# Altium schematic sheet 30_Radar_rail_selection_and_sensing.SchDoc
size 289 x 396 mm
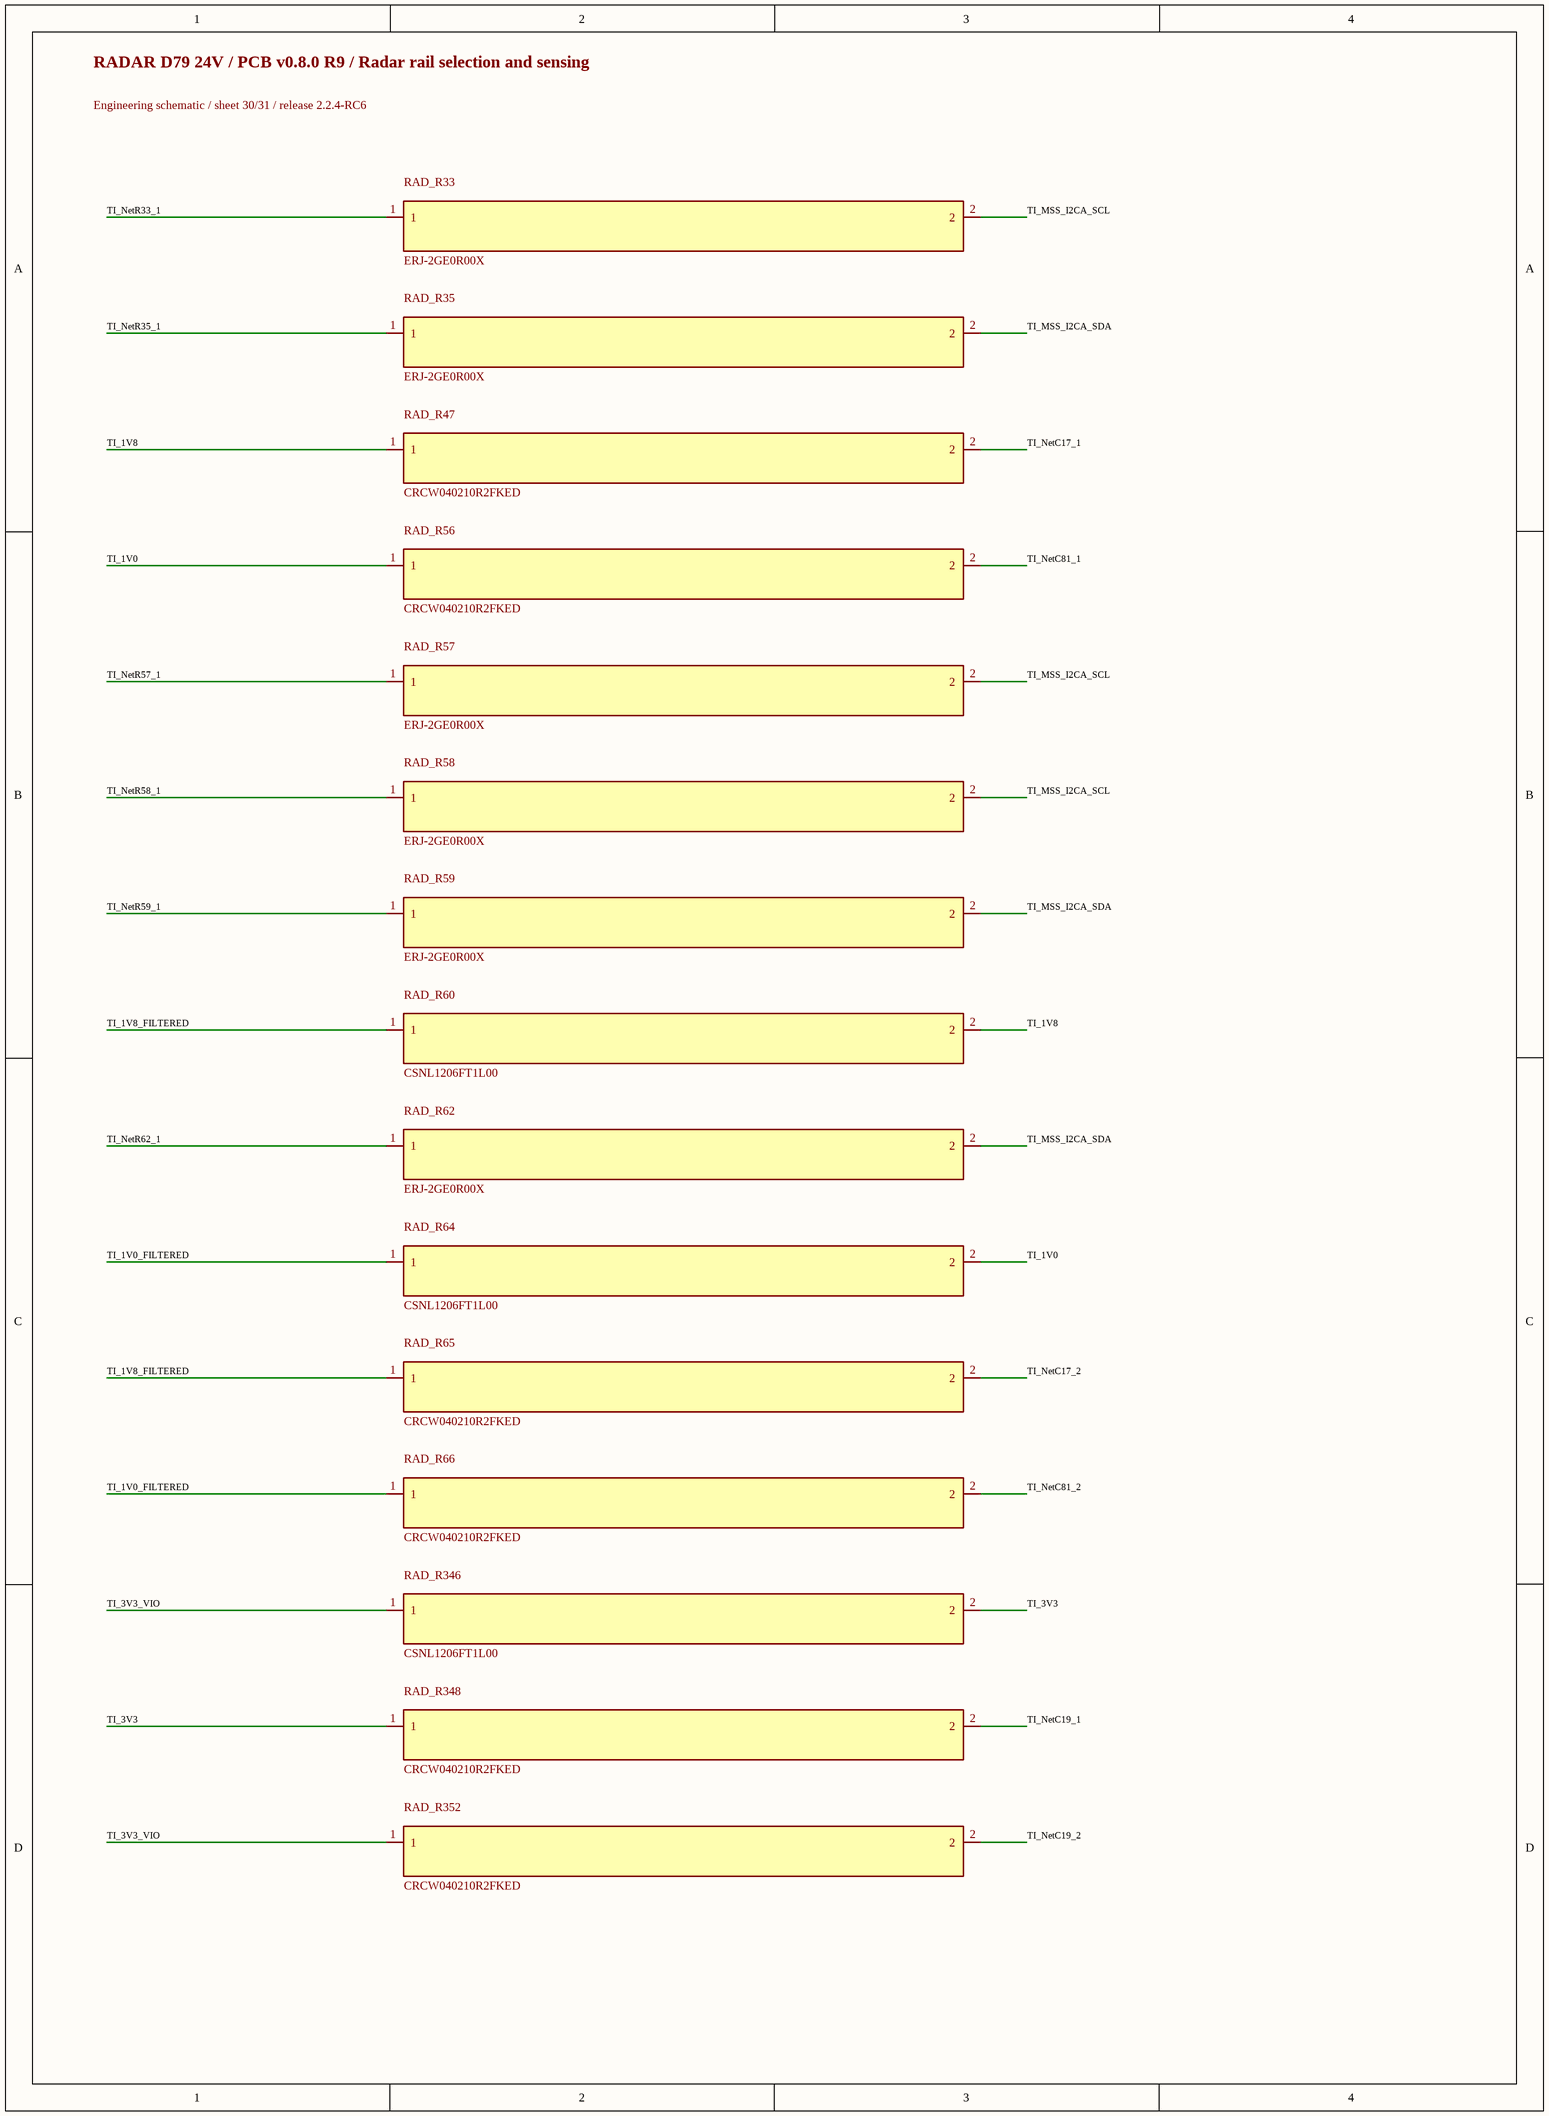
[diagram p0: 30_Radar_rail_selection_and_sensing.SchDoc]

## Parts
RAD_R33  ERJ-2GE0R00X  [0402L]
RAD_R35  ERJ-2GE0R00X  [0402L]
RAD_R47  CRCW040210R2FKED  [0402L]
RAD_R56  CRCW040210R2FKED  [0402L]
RAD_R57  ERJ-2GE0R00X  [0402L]
RAD_R58  ERJ-2GE0R00X  [0402L]
RAD_R59  ERJ-2GE0R00X  [0402L]
RAD_R60  CSNL1206FT1L00  [1206L]
RAD_R62  ERJ-2GE0R00X  [0402L]
RAD_R64  CSNL1206FT1L00  [1206L]
RAD_R65  CRCW040210R2FKED  [0402L]
RAD_R66  CRCW040210R2FKED  [0402L]
RAD_R346  CSNL1206FT1L00  [1206L]
RAD_R348  CRCW040210R2FKED  [0402L]
RAD_R352  CRCW040210R2FKED  [0402L]

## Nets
TI_1V0: RAD_R56.1 RAD_R64.2
TI_1V0_FILTERED: RAD_R64.1 RAD_R66.1
TI_1V8: RAD_R47.1 RAD_R60.2
TI_1V8_FILTERED: RAD_R60.1 RAD_R65.1
TI_3V3: RAD_R346.2 RAD_R348.1
TI_3V3_VIO: RAD_R346.1 RAD_R352.1
TI_MSS_I2CA_SCL: RAD_R33.2 RAD_R57.2 RAD_R58.2
TI_MSS_I2CA_SDA: RAD_R35.2 RAD_R59.2 RAD_R62.2
TI_NetC17_1: RAD_R47.2
TI_NetC17_2: RAD_R65.2
TI_NetC19_1: RAD_R348.2
TI_NetC19_2: RAD_R352.2
TI_NetC81_1: RAD_R56.2
TI_NetC81_2: RAD_R66.2
TI_NetR33_1: RAD_R33.1
TI_NetR35_1: RAD_R35.1
TI_NetR57_1: RAD_R57.1
TI_NetR58_1: RAD_R58.1
TI_NetR59_1: RAD_R59.1
TI_NetR62_1: RAD_R62.1

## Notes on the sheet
- RADAR D79 24V / PCB v0.8.0 R9 / Radar rail selection and sensing
- Engineering schematic / sheet 30/31 / release 2.2.4-RC6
